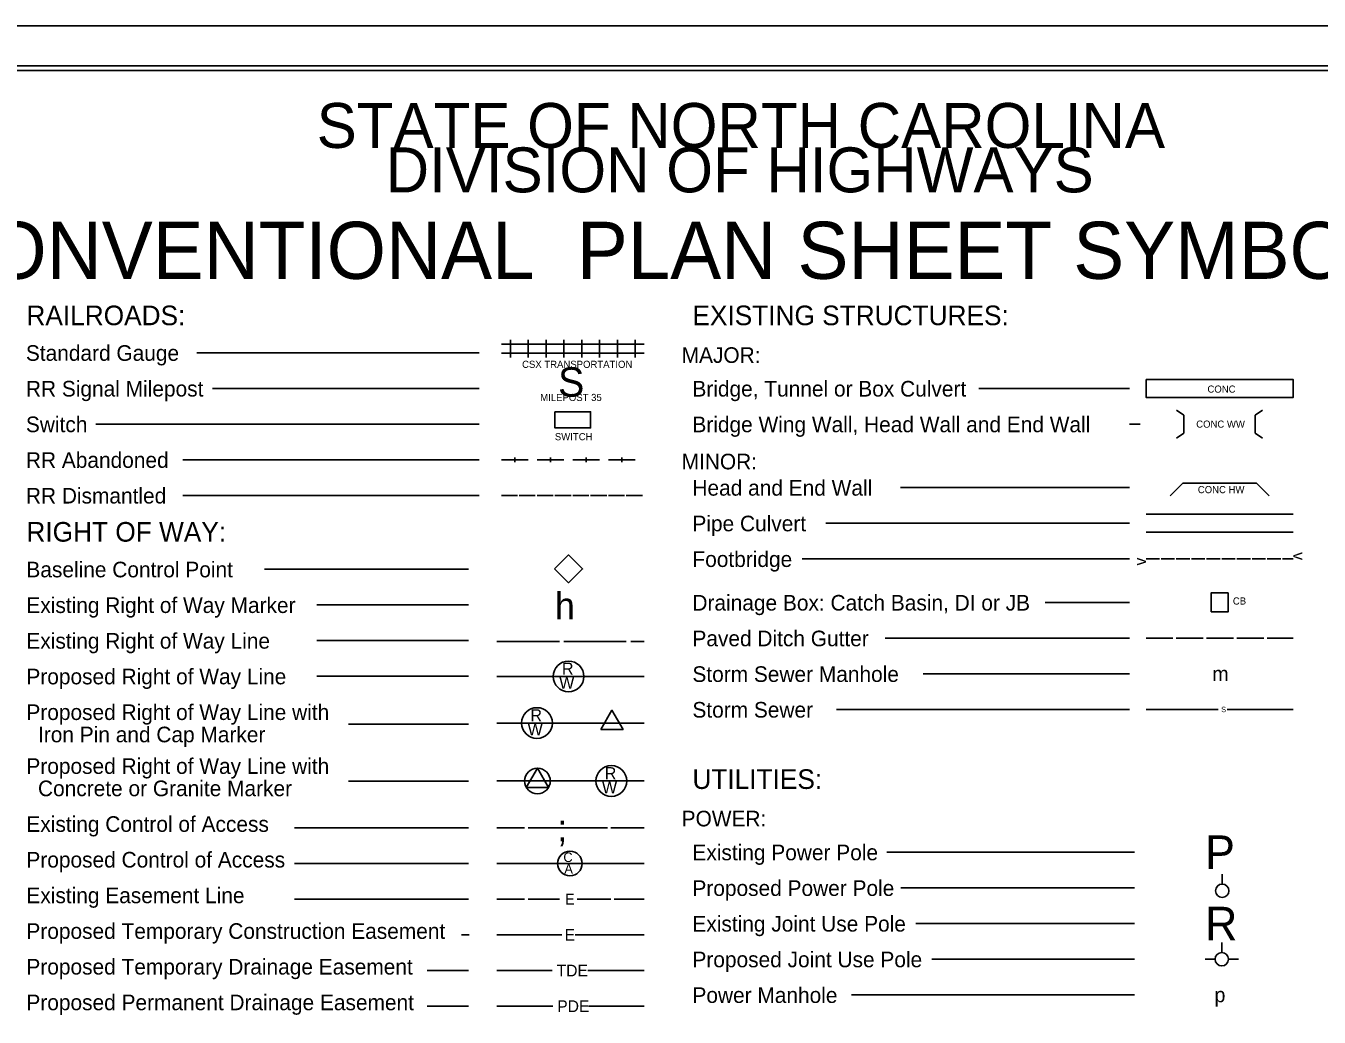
# Model space of a CAD drawing. Extents: x 573855 to 575539, y -53293 to -50956.
# Drawn here: x 574417 to 575142, y -52749 to -52193 of the extents above; entities that cross this region are included whole.
import ezdxf

# ---------------------------------------------------------------- set-up
doc = ezdxf.new("R2010")
doc.units = 0
for name, color, linetype in [('Default', 7, 'Continuous'), ('Sheet Cutting Line CELL', 7, 'Continuous'), ('Sheet Plot Border Inside CELL', 7, 'Continuous'), ('Sheet Plot Border Outside CELL', 7, 'Continuous'), ('Sheet Symbology CELL', 7, 'Continuous')]:
    doc.layers.add(name, color=color, linetype=linetype)

msp = doc.modelspace()

# ---------------------------------------------------------------- linework, layer by layer
at = {"layer": 'Default'}
msp.add_lwpolyline([(574713.23, -52497.92), (574721.05, -52490.1), (574728.87, -52497.92), (574721.05, -52505.75)], close=True, dxfattribs=at)
at = {"layer": 'Sheet Cutting Line CELL'}
msp.add_line((575539.41, -52193.48), (573855.41, -52193.48), dxfattribs=at)
at = {"layer": 'Sheet Plot Border Inside CELL'}
msp.add_lwpolyline([(573868.41, -53271.03), (575534.91, -53271.03), (575534.91, -52215.93), (573868.41, -52215.93)], close=True, dxfattribs=at)
at = {"layer": 'Sheet Plot Border Outside CELL'}
msp.add_lwpolyline([(573855.41, -53293.48), (575539.41, -53293.48), (575539.41, -52193.48), (573855.41, -52193.48)], close=True, dxfattribs=at)
at = {"layer": 'Sheet Symbology CELL'}
for p, q in [((574688.41, -52379.51), (574688.41, -52369.51)), ((574698.41, -52379.51), (574698.41, -52369.51)), ((574708.41, -52379.51), (574708.41, -52369.51)), ((574718.41, -52379.51), (574718.41, -52369.51)), ((574728.41, -52379.51), (574728.41, -52369.51)), ((574738.41, -52379.51), (574738.41, -52369.51)), ((574748.41, -52379.51), (574748.41, -52369.51)), ((574758.41, -52379.51), (574758.41, -52369.51)), ((574671.01, -52376.77), (574512.6, -52376.77)), ((574683.41, -52372.01), (574693.41, -52372.01)), ((574683.41, -52377.01), (574693.41, -52377.01)), ((574693.41, -52372.01), (574703.41, -52372.01)), ((574693.41, -52377.01), (574703.41, -52377.01)), ((574703.41, -52372.01), (574713.41, -52372.01)), ((574703.41, -52377.01), (574713.41, -52377.01)), ((574713.41, -52372.01), (574723.41, -52372.01)), ((574713.41, -52377.01), (574723.41, -52377.01)), ((574723.41, -52372.01), (574733.41, -52372.01)), ((574723.41, -52377.01), (574733.41, -52377.01)), ((574733.41, -52372.01), (574743.41, -52372.01)), ((574733.41, -52377.01), (574743.41, -52377.01)), ((574743.41, -52372.01), (574753.41, -52372.01)), ((574743.41, -52377.01), (574753.41, -52377.01)), ((574753.41, -52372.01), (574763.41, -52372.01)), ((574753.41, -52377.01), (574763.41, -52377.01)), ((574671.01, -52396.77), (574521.46, -52396.77)), ((575035.42, -52396.77), (574951, -52396.77)), ((575061.87, -52408.91), (575065.97, -52411.77)), ((575065.97, -52411.77), (575065.97, -52421.77)), ((575110.07, -52408.91), (575105.97, -52411.77)), ((575105.97, -52411.77), (575105.97, -52421.77)), ((574671.01, -52416.77), (574456.1, -52416.77)), ((575035.42, -52416.77), (575041.41, -52416.77)), ((575061.87, -52424.63), (575065.97, -52421.77)), ((575110.07, -52424.63), (575105.97, -52421.77)), ((574671.01, -52436.77), (574504.85, -52436.77)), ((574683.41, -52436.77), (574698.41, -52436.77)), ((574690.91, -52435.52), (574690.91, -52438.02)), ((574703.41, -52436.77), (574718.41, -52436.77)), ((574710.91, -52435.52), (574710.91, -52438.02)), ((574723.41, -52436.77), (574738.41, -52436.77)), ((574730.91, -52435.52), (574730.91, -52438.02)), ((574743.41, -52436.77), (574758.41, -52436.77)), ((574750.91, -52435.52), (574750.91, -52438.02)), ((574671.01, -52456.77), (574504.85, -52456.77)), ((574671.01, -52456.77), (574504.85, -52456.77)), ((574683.41, -52456.77), (574692.41, -52456.77)), ((574693.41, -52456.77), (574702.41, -52456.77)), ((574703.41, -52456.77), (574712.41, -52456.77)), ((574713.41, -52456.77), (574722.41, -52456.77)), ((574723.41, -52456.77), (574732.41, -52456.77)), ((574733.41, -52456.77), (574742.41, -52456.77)), ((574743.41, -52456.77), (574752.41, -52456.77)), ((574753.41, -52456.77), (574762.41, -52456.77)), ((575035.42, -52452.34), (574907.12, -52452.34)), ((575058.27, -52456.91), (575065.35, -52449.84)), ((575065.35, -52449.84), (575106.6, -52449.84)), ((575106.6, -52449.84), (575113.67, -52456.91)), ((575044.72, -52467.34), (575127.22, -52467.34)), ((575035.42, -52472.34), (574865.23, -52472.34)), ((575044.72, -52477.34), (575127.22, -52477.34)), ((575035.42, -52492.34), (574851.95, -52492.34)), ((575044.72, -52492.34), (575052.22, -52492.34)), ((575053.22, -52492.34), (575060.72, -52492.34)), ((575061.72, -52492.34), (575069.22, -52492.34)), ((575070.22, -52492.34), (575077.72, -52492.34)), ((575078.72, -52492.34), (575086.22, -52492.34)), ((575087.22, -52492.34), (575094.72, -52492.34)), ((575095.72, -52492.34), (575103.22, -52492.34)), ((575104.22, -52492.34), (575111.72, -52492.34)), ((575112.72, -52492.34), (575120.22, -52492.34)), ((575121.22, -52492.34), (575127.22, -52492.34)), ((574664.88, -52498.12), (574550.66, -52498.12)), ((574664.88, -52518.12), (574579.94, -52518.12)), ((575035.42, -52516.77), (574988.22, -52516.77)), ((574664.88, -52538.12), (574579.94, -52538.12)), ((574680.91, -52538.69), (574715.91, -52538.69)), ((574718.41, -52538.69), (574753.41, -52538.69)), ((574755.91, -52538.69), (574763.41, -52538.69)), ((575035.42, -52536.77), (574898.47, -52536.77)), ((575044.72, -52536.77), (575059.72, -52536.77)), ((575061.72, -52536.77), (575076.72, -52536.77)), ((575078.72, -52536.77), (575093.72, -52536.77)), ((575095.72, -52536.77), (575110.72, -52536.77)), ((575112.72, -52536.77), (575127.22, -52536.77)), ((574664.88, -52558.12), (574579.94, -52558.12)), ((574680.91, -52558.24), (574763.41, -52558.24)), ((575035.42, -52556.77), (574919.75, -52556.77)), ((575035.42, -52576.77), (574871.22, -52576.77)), ((575044.72, -52576.77), (575085.25, -52576.77)), ((575090.25, -52576.77), (575127.22, -52576.77)), ((574664.88, -52584.97), (574597.76, -52584.97)), ((574680.91, -52584.37), (574763.41, -52584.37)), ((574745.36, -52584.37), (574745.36, -52584.37)), ((574664.88, -52617.01), (574597.76, -52617.01)), ((574680.91, -52616.87), (574763.41, -52616.87)), ((574703.61, -52616.87), (574703.61, -52616.87)), ((574664.88, -52643.12), (574567.33, -52643.12)), ((574680.91, -52643.12), (574696.37, -52643.12)), ((574698.37, -52643.12), (574742.78, -52643.12)), ((574744.78, -52643.12), (574763.41, -52643.12)), ((575038.21, -52656.77), (574899.51, -52656.77)), ((574664.88, -52663.12), (574567.33, -52663.12)), ((574680.91, -52663.12), (574763.41, -52663.12)), ((575087.43, -52674.66), (575087.43, -52669.03)), ((575038.21, -52676.77), (574907.3, -52676.77)), ((574664.88, -52683.12), (574567.33, -52683.12)), ((574680.91, -52683.12), (574696.42, -52683.12)), ((574698.42, -52683.12), (574715.92, -52683.12)), ((574725.92, -52683.12), (574744.67, -52683.12)), ((574746.67, -52683.12), (574763.41, -52683.12)), ((574665.26, -52703.12), (574661.09, -52703.12)), ((574680.91, -52703.12), (574683.52, -52703.12)), ((574683.52, -52703.12), (574717.27, -52703.12)), ((574724.77, -52703.12), (574758.52, -52703.12)), ((574758.52, -52703.12), (574763.41, -52703.12)), ((575038.21, -52696.77), (574915.7, -52696.77)), ((575087.22, -52713.01), (575087.22, -52707.38)), ((575038.21, -52716.77), (574924.7, -52716.77)), ((575083.47, -52716.76), (575077.85, -52716.76)), ((575090.97, -52716.76), (575096.6, -52716.76)), ((574664.88, -52723.12), (574641.73, -52723.12)), ((574680.91, -52723.12), (574684.26, -52723.12)), ((574684.26, -52723.12), (574711.76, -52723.12)), ((574731.76, -52723.12), (574759.26, -52723.12)), ((574759.26, -52723.12), (574763.41, -52723.12)), ((575038.21, -52736.77), (574879.71, -52736.77)), ((574664.88, -52743.12), (574641.73, -52743.12)), ((574680.91, -52743.12), (574684.71, -52743.12)), ((574684.71, -52743.12), (574712.21, -52743.12)), ((574732.21, -52743.12), (574759.71, -52743.12)), ((574759.71, -52743.12), (574763.41, -52743.12))]:
    msp.add_line(p, q, dxfattribs=at)
for points in [[(575522.41, -52218.48), (574022.41, -52218.48), (574022.41, -53268.48), (575522.41, -53268.48)], [(574713.41, -52409.81), (574733.41, -52409.81), (574733.41, -52418.91), (574713.41, -52418.91)], [(575081.16, -52522.08), (575090.77, -52522.08), (575090.77, -52511.44), (575081.16, -52511.44)], [(574739.11, -52587.97), (574745.36, -52577.17), (574751.61, -52587.97)], [(574697.36, -52620.47), (574703.61, -52609.67), (574709.86, -52620.47)]]:
    msp.add_lwpolyline(points, close=True, dxfattribs=at)
msp.add_lwpolyline([(575044.72, -52391.77), (575127.22, -52391.77), (575127.22, -52401.77), (575044.72, -52401.77), (575044.72, -52391.77)], dxfattribs=at)
for centre, radius in [((574721.03, -52558.24), 8.61), ((574703.33, -52584.37), 8.61), ((574745, -52616.87), 8.61), ((574703.6, -52616.87), 7.2), ((574721.78, -52663.12), 6.89), ((575087.43, -52678.41), 3.75), ((575087.22, -52716.77), 3.75)]:
    msp.add_circle(centre, radius, dxfattribs=at)

# ---------------------------------------------------------------- texts
for s, height, p in [('STATE OF NORTH CAROLINA', 25.1988, (574579.86, -52261.93)), ('DIVISION OF HIGHWAYS', 25.1988, (574618.51, -52286.83)), ('CONVENTIONAL  PLAN SHEET SYMBOLS', 32.0004, (574364.3, -52335.33)), ('RAILROADS:', 11, (574417.13, -52361.32)), ('EXISTING STRUCTURES:', 11, (574790.46, -52361.32)), ('Standard Gauge', 8.75, (574416.85, -52381.29)), ('MAJOR:', 8.75, (574784.43, -52382.43)), ('S', 16.5, (574715.17, -52401.39)), ('RR Signal Milepost', 8.75, (574416.85, -52401.29)), ('Bridge, Tunnel or Box Culvert', 8.75, (574790.46, -52401.32)), ('CONC', 4, (575079.16, -52399.13)), ('Switch', 8.75, (574416.85, -52421.29)), ('Bridge Wing Wall, Head Wall and End Wall', 8.75, (574790.46, -52421.32)), ('RR Abandoned', 8.75, (574416.85, -52441.29)), ('MINOR:', 8.75, (574784.43, -52442.13)), ('Head and End Wall', 8.75, (574790.46, -52456.89)), ('RR Dismantled', 8.75, (574416.85, -52461.29)), ('Pipe Culvert', 8.75, (574790.46, -52476.87)), ('RIGHT OF WAY:', 11, (574417.13, -52482.67)), ('Footbridge', 8.75, (574790.47, -52496.87)), ('Baseline Control Point', 8.75, (574417.13, -52502.67)), ('Existing Right of Way Marker', 8.75, (574417.13, -52522.67)), ('h', 15, (574713.42, -52526.19)), ('Drainage Box: Catch Basin, DI or JB', 8.75, (574790.47, -52521.31)), ('Existing Right of Way Line', 8.75, (574417.13, -52542.67)), ('Paved Ditch Gutter', 8.75, (574790.47, -52541.32)), ('R', 6.75, (574717.32, -52557.23)), ('Proposed Right of Way Line', 8.75, (574417.13, -52562.67)), ('Storm Sewer Manhole', 8.75, (574790.47, -52561.32)), ('m', 8.25, (575081.85, -52560.89)), ('W', 6.75, (574715.78, -52565.18)), ('Storm Sewer', 8.75, (574790.47, -52581.32)), ('Proposed Right of Way Line with', 8.75, (574417.13, -52582.67)), ('R', 6.75, (574699.62, -52583.36)), ('S', 3, (575086.85, -52578.27)), ('  Iron Pin and Cap Marker', 8.75, (574417.13, -52595.17)), ('W', 6.75, (574698.08, -52591.31)), ('Proposed Right of Way Line with', 8.75, (574417.13, -52612.88)), ('  Concrete or Granite Marker', 8.75, (574417.13, -52625.38)), ('R', 6.75, (574741.29, -52615.86)), ('UTILITIES:', 11, (574790.46, -52621.32)), ('W', 6.75, (574739.76, -52623.81)), ('Existing Control of Access', 8.75, (574417.13, -52645.38)), ('POWER:', 8.75, (574784.43, -52642.31)), (';', 15, (574714.66, -52650.62)), ('Existing Power Pole', 8.75, (574790.47, -52661.31)), ('P', 18.75, (575077.85, -52666.14)), ('Proposed Control of Access', 8.75, (574417.13, -52665.38)), ('C', 5.4, (574718.12, -52662.31)), ('A', 5.4, (574718.66, -52668.79)), ('Proposed Power Pole', 8.75, (574790.47, -52681.31)), ('Existing Easement Line', 8.75, (574417.13, -52685.38)), ('E', 6, (574719.12, -52686.12)), ('R', 18.75, (575077.85, -52706.14)), ('Existing Joint Use Pole', 8.75, (574790.47, -52701.29)), ('Proposed Temporary Construction Easement', 8.75, (574417.13, -52705.38)), ('E', 6.55, (574718.87, -52706.42)), ('Proposed Temporary Drainage Easement', 8.75, (574417.13, -52725.38)), ('Proposed Joint Use Pole', 8.75, (574790.48, -52721.31)), ('TDE', 6.55, (574714.36, -52726.42)), ('Power Manhole', 8.75, (574790.48, -52741.31)), ('Proposed Permanent Drainage Easement', 8.75, (574417.13, -52745.38)), ('p', 8.25, (575083.1, -52740.89)), ('PDE', 6.55, (574714.71, -52746.42))]:
    msp.add_text(s, height=height, dxfattribs=at).set_placement(p)
for s, height, rotation, p in [('CSX TRANSPORTATION', 4, 360, (574694.97, -52385.24)), ('MILEPOST 35', 4, 360, (574705.16, -52403.82)), ('CONC WW', 4, 0.00002, (575072.85, -52418.77)), ('SWITCH', 4, 360, (574713.36, -52425.82)), ('CONC HW', 4, 360, (575073.77, -52455.5)), ('v', 6.6, 89.75915, (575044.71, -52496.07)), ('v', 6.6, 270.24085, (575127.21, -52488.6)), ('CB', 4, 360, (575093.41, -52517.94))]:
    msp.add_text(s, height=height, rotation=rotation, dxfattribs=at).set_placement(p)

doc.saveas('drawing.dxf')
